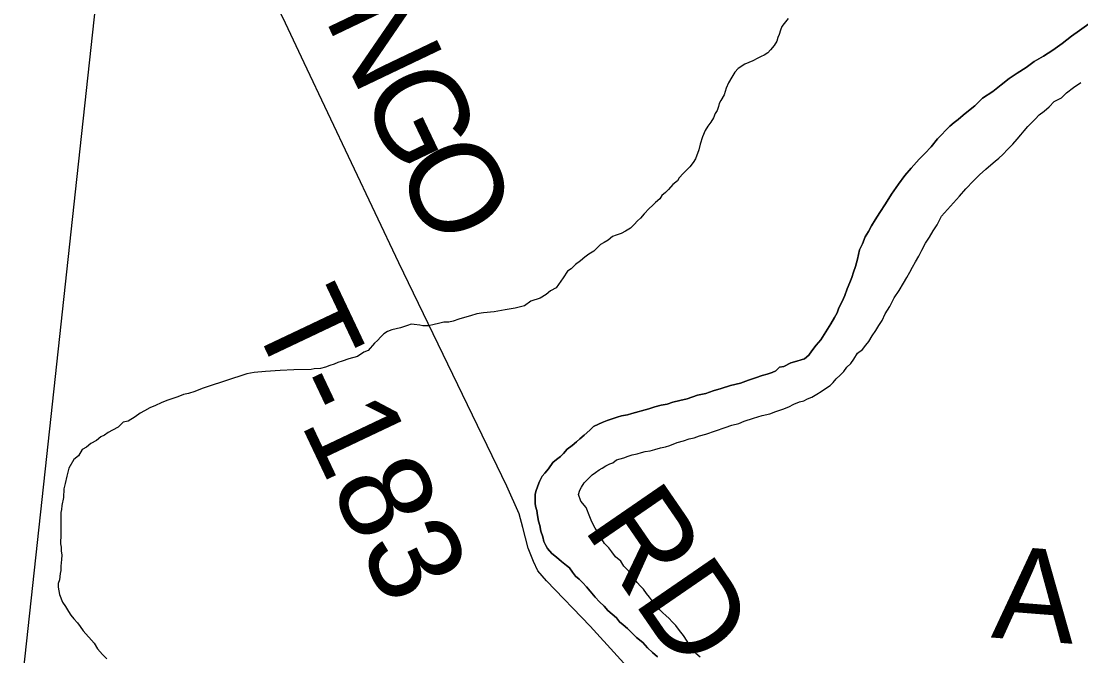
# Model space of a CAD drawing. Extents: x 0 to 34, y 0 to 22.
# Drawn here: x 4.269 to 4.921, y 16.386 to 16.776 of the extents above; entities that cross this region are included whole.
import ezdxf

# ---------------------------------------------------------------- set-up
doc = ezdxf.new("R2010")
doc.units = 0
for name, color, linetype in [('GM_X_Major_River', 7, 'Continuous'), ('GM_X_Minor_River', 7, 'Continuous'), ('GM_X_State_Route', 7, 'Continuous'), ('GM_X_Township_Road', 7, 'Continuous'), ('GM_X_Township_Road_Text', 7, 'Continuous')]:
    doc.layers.add(name, color=color, linetype=linetype)

msp = doc.modelspace()

# ---------------------------------------------------------------- linework, layer by layer
at = {"layer": 'GM_X_Major_River'}
for points in [[(4.92578, 16.77455), (4.92003, 16.77043), (4.91505, 16.76707), (4.90929, 16.76258), (4.90354, 16.75846), (4.89779, 16.75473), (4.89205, 16.75138), (4.88706, 16.74763), (4.8817, 16.74428), (4.87672, 16.74091), (4.87173, 16.73717), (4.86674, 16.73305), (4.86023, 16.72895), (4.85561, 16.72406), (4.85177, 16.72107), (4.84832, 16.71844), (4.84525, 16.71582), (4.84294, 16.71395), (4.84026, 16.7117), (4.83256, 16.70381), (4.8287, 16.69891), (4.82485, 16.69477), (4.82138, 16.69139), (4.81637, 16.68575), (4.81252, 16.68124), (4.80865, 16.67596), (4.8044, 16.66993), (4.80053, 16.66389), (4.79704, 16.65861), (4.79433, 16.65408), (4.792, 16.65031), (4.79006, 16.64691), (4.78812, 16.64351), (4.78655, 16.63935), (4.7846, 16.63557), (4.78339, 16.62988), (4.78219, 16.62534)], [(4.78219, 16.62534), (4.78339, 16.62988), (4.7846, 16.63557), (4.78655, 16.63935), (4.78812, 16.64351), (4.79006, 16.64691), (4.792, 16.65031), (4.79433, 16.65408), (4.79704, 16.65861), (4.80053, 16.66389), (4.8044, 16.66993), (4.80865, 16.67596), (4.81252, 16.68124), (4.81637, 16.68575), (4.82138, 16.69139), (4.82485, 16.69477), (4.8287, 16.69891), (4.83256, 16.70381), (4.84026, 16.7117), (4.84294, 16.71395), (4.84525, 16.71582), (4.84832, 16.71844), (4.85177, 16.72107), (4.85561, 16.72406), (4.86023, 16.72895), (4.86674, 16.73305), (4.87173, 16.73717), (4.87672, 16.74091), (4.8817, 16.74428), (4.88706, 16.74763), (4.89205, 16.75138), (4.89779, 16.75473), (4.90354, 16.75846), (4.90929, 16.76258), (4.91505, 16.76707), (4.92003, 16.77043), (4.92578, 16.77455)], [(4.89815, 16.7209), (4.90122, 16.72352), (4.9043, 16.7269), (4.90889, 16.72913), (4.91197, 16.73214), (4.91619, 16.73551), (4.92079, 16.73849)], [(4.89815, 16.7209), (4.90122, 16.72352), (4.9043, 16.7269), (4.90889, 16.72913), (4.91197, 16.73214), (4.91619, 16.73551), (4.92079, 16.73849)], [(4.61657, 16.47715), (4.6132, 16.48099), (4.61173, 16.48519), (4.61252, 16.48784), (4.61369, 16.48973), (4.61524, 16.49237), (4.61793, 16.495), (4.62024, 16.49725), (4.62215, 16.49875), (4.62445, 16.50024), (4.62637, 16.50136), (4.62867, 16.50286), (4.63096, 16.50397), (4.63287, 16.50471), (4.63518, 16.50658), (4.63975, 16.50766), (4.64242, 16.50877), (4.64471, 16.50951), (4.64776, 16.51023), (4.65043, 16.51096), (4.65272, 16.51169), (4.65577, 16.51204), (4.65882, 16.51276), (4.66225, 16.51386), (4.6653, 16.51458), (4.66797, 16.51531), (4.67256, 16.51716), (4.67637, 16.51826), (4.6798, 16.51935), (4.68285, 16.52008), (4.68629, 16.52118), (4.6901, 16.52227), (4.70194, 16.52632), (4.70614, 16.52779), (4.71033, 16.52888), (4.71377, 16.53036), (4.71949, 16.53219), (4.72483, 16.53365), (4.72941, 16.53473), (4.73323, 16.53621), (4.73743, 16.53768), (4.74124, 16.53915), (4.7443, 16.54064), (4.74774, 16.54212), (4.75041, 16.54284), (4.75271, 16.54396), (4.75538, 16.54507), (4.75844, 16.54693), (4.76112, 16.54842), (4.76381, 16.55029), (4.76649, 16.55216), (4.76841, 16.55404), (4.77034, 16.55629), (4.77265, 16.55855), (4.77496, 16.5608), (4.77689, 16.56344), (4.7792, 16.56569), (4.78113, 16.56833), (4.78345, 16.5721), (4.78652, 16.57435), (4.78846, 16.57699), (4.79038, 16.57924), (4.79233, 16.58264), (4.79465, 16.58604), (4.79658, 16.58905), (4.79852, 16.59207), (4.80047, 16.59623), (4.80319, 16.60076), (4.80591, 16.60605), (4.80901, 16.61057), (4.81172, 16.6151), (4.81366, 16.6185), (4.81561, 16.6219), (4.81716, 16.62492), (4.8191, 16.62832), (4.82105, 16.63172), (4.82299, 16.6355), (4.82532, 16.63965), (4.82765, 16.64342), (4.82997, 16.6472), (4.8323, 16.65097), (4.83502, 16.65626), (4.8462, 16.66867), (4.85005, 16.67319), (4.85468, 16.67808), (4.85852, 16.68183), (4.86236, 16.68521), (4.86544, 16.68783), (4.86812, 16.69008), (4.87043, 16.69195), (4.87274, 16.69421), (4.87582, 16.69759), (4.8789, 16.7006), (4.88159, 16.70361), (4.8839, 16.70624), (4.88584, 16.70888), (4.88815, 16.71151), (4.89046, 16.71376), (4.89277, 16.71602), (4.89508, 16.71865), (4.89815, 16.7209)], [(4.61657, 16.47715), (4.6132, 16.48099), (4.61173, 16.48519), (4.61252, 16.48784), (4.61369, 16.48973), (4.61524, 16.49237), (4.61793, 16.495), (4.62024, 16.49725), (4.62215, 16.49875), (4.62445, 16.50024), (4.62637, 16.50136), (4.62867, 16.50286), (4.63096, 16.50397), (4.63287, 16.50471), (4.63518, 16.50658), (4.63975, 16.50766), (4.64242, 16.50877), (4.64471, 16.50951), (4.64776, 16.51023), (4.65043, 16.51096), (4.65272, 16.51169), (4.65577, 16.51204), (4.65882, 16.51276), (4.66225, 16.51386), (4.6653, 16.51458), (4.66797, 16.51531), (4.67256, 16.51716), (4.67637, 16.51826), (4.6798, 16.51935), (4.68285, 16.52008), (4.68629, 16.52118), (4.6901, 16.52227), (4.70194, 16.52632), (4.70614, 16.52779), (4.71033, 16.52888), (4.71377, 16.53036), (4.71949, 16.53219), (4.72483, 16.53365), (4.72941, 16.53473), (4.73323, 16.53621), (4.73743, 16.53768), (4.74124, 16.53915), (4.7443, 16.54064), (4.74774, 16.54212), (4.75041, 16.54284), (4.75271, 16.54396), (4.75538, 16.54507), (4.75844, 16.54693), (4.76112, 16.54842), (4.76381, 16.55029), (4.76649, 16.55216), (4.76841, 16.55404), (4.77034, 16.55629), (4.77265, 16.55855), (4.77496, 16.5608), (4.77689, 16.56344), (4.7792, 16.56569), (4.78113, 16.56833), (4.78345, 16.5721), (4.78652, 16.57435), (4.78846, 16.57699), (4.79038, 16.57924), (4.79233, 16.58264), (4.79465, 16.58604), (4.79658, 16.58905), (4.79852, 16.59207), (4.80047, 16.59623), (4.80319, 16.60076), (4.80591, 16.60605), (4.80901, 16.61057), (4.81172, 16.6151), (4.81366, 16.6185), (4.81561, 16.6219), (4.81716, 16.62492), (4.8191, 16.62832), (4.82105, 16.63172), (4.82299, 16.6355), (4.82532, 16.63965), (4.82765, 16.64342), (4.82997, 16.6472), (4.8323, 16.65097), (4.83502, 16.65626), (4.8462, 16.66867), (4.85005, 16.67319), (4.85468, 16.67808), (4.85852, 16.68183), (4.86236, 16.68521), (4.86544, 16.68783), (4.86812, 16.69008), (4.87043, 16.69195), (4.87274, 16.69421), (4.87582, 16.69759), (4.8789, 16.7006), (4.88159, 16.70361), (4.8839, 16.70624), (4.88584, 16.70888), (4.88815, 16.71151), (4.89046, 16.71376), (4.89277, 16.71602), (4.89508, 16.71865), (4.89815, 16.7209)], [(4.78219, 16.62534), (4.78101, 16.62193), (4.77983, 16.61852), (4.77865, 16.6155), (4.77709, 16.61171), (4.77552, 16.60755), (4.77395, 16.60377), (4.77201, 16.59999), (4.77083, 16.59696), (4.76927, 16.59394), (4.76695, 16.59017), (4.76075, 16.58036), (4.75805, 16.57697), (4.75534, 16.57358), (4.75341, 16.57094), (4.75072, 16.56869), (4.74881, 16.56795), (4.74614, 16.56722), (4.74233, 16.56613), (4.73812, 16.5639), (4.73546, 16.56355), (4.73315, 16.5613), (4.73085, 16.56018), (4.7278, 16.55908), (4.72475, 16.55836), (4.72055, 16.55688), (4.71635, 16.55541), (4.71139, 16.55357), (4.70529, 16.55212), (4.69956, 16.55029), (4.6946, 16.54883), (4.69003, 16.54736), (4.68507, 16.54628), (4.67858, 16.54408), (4.67401, 16.54299), (4.66981, 16.5419), (4.66638, 16.5408), (4.66257, 16.54009), (4.65875, 16.53899), (4.65494, 16.5379), (4.64464, 16.53498), (4.64197, 16.53425), (4.63816, 16.53353), (4.63549, 16.5328), (4.63244, 16.5317), (4.62938, 16.5306), (4.62633, 16.52949), (4.62403, 16.52838), (4.62097, 16.5269), (4.61867, 16.52464), (4.61521, 16.52164), (4.61252, 16.51939), (4.6106, 16.51751), (4.60791, 16.51527), (4.60484, 16.51302), (4.60253, 16.51039), (4.60061, 16.50851), (4.5983, 16.50664), (4.596, 16.50476), (4.59329, 16.50099), (4.59098, 16.49836), (4.58944, 16.49648), (4.58787, 16.49308), (4.5867, 16.49043), (4.58552, 16.48702), (4.58512, 16.48513), (4.58509, 16.48284), (4.58505, 16.4798), (4.58541, 16.4779), (4.58614, 16.47523), (4.58648, 16.47219), (4.5872, 16.46875), (4.58793, 16.46609), (4.58865, 16.46266), (4.58975, 16.45922), (4.59047, 16.45617), (4.59159, 16.45388), (4.5927, 16.45196), (4.59533, 16.44889), (4.59834, 16.44658), (4.60135, 16.44388), (4.60436, 16.44156), (4.60624, 16.44002), (4.60811, 16.43734), (4.60999, 16.43503), (4.61224, 16.43311), (4.6145, 16.4308), (4.61675, 16.42849), (4.619, 16.4258), (4.62199, 16.42197), (4.62462, 16.41927), (4.62763, 16.41658), (4.62988, 16.41389), (4.63251, 16.41158), (4.63515, 16.40927), (4.63702, 16.40696), (4.63928, 16.40504), (4.64191, 16.40272), (4.64454, 16.40003), (4.64755, 16.39733), (4.65131, 16.39425)], [(4.65131, 16.39425), (4.64755, 16.39733), (4.64454, 16.40003), (4.64191, 16.40272), (4.63928, 16.40504), (4.63702, 16.40696), (4.63515, 16.40927), (4.63251, 16.41158), (4.62988, 16.41389), (4.62763, 16.41658), (4.62462, 16.41927), (4.62199, 16.42197), (4.619, 16.4258), (4.61675, 16.42849), (4.6145, 16.4308), (4.61224, 16.43311), (4.60999, 16.43503), (4.60811, 16.43734), (4.60624, 16.44002), (4.60436, 16.44156), (4.60135, 16.44388), (4.59834, 16.44658), (4.59533, 16.44889), (4.5927, 16.45196), (4.59159, 16.45388), (4.59047, 16.45617), (4.58975, 16.45922), (4.58865, 16.46266), (4.58793, 16.46609), (4.5872, 16.46875), (4.58648, 16.47219), (4.58614, 16.47523), (4.58541, 16.4779), (4.58505, 16.4798), (4.58509, 16.48284), (4.58512, 16.48513), (4.58552, 16.48702), (4.5867, 16.49043), (4.58787, 16.49308), (4.58944, 16.49648), (4.59098, 16.49836), (4.59329, 16.50099), (4.596, 16.50476), (4.5983, 16.50664), (4.60061, 16.50851), (4.60253, 16.51039), (4.60484, 16.51302), (4.60791, 16.51527), (4.6106, 16.51751), (4.61252, 16.51939), (4.61521, 16.52164), (4.61867, 16.52464), (4.62097, 16.5269), (4.62403, 16.52838), (4.62633, 16.52949), (4.62938, 16.5306), (4.63244, 16.5317), (4.63549, 16.5328), (4.63816, 16.53353), (4.64197, 16.53425), (4.64464, 16.53498), (4.65494, 16.5379), (4.65875, 16.53899), (4.66257, 16.54009), (4.66638, 16.5408), (4.66981, 16.5419), (4.67401, 16.54299), (4.67858, 16.54408), (4.68507, 16.54628), (4.69003, 16.54736), (4.6946, 16.54883), (4.69956, 16.55029), (4.70529, 16.55212), (4.71139, 16.55357), (4.71635, 16.55541), (4.72055, 16.55688), (4.72475, 16.55836), (4.7278, 16.55908), (4.73085, 16.56018), (4.73315, 16.5613), (4.73546, 16.56355), (4.73812, 16.5639), (4.74233, 16.56613), (4.74614, 16.56722), (4.74881, 16.56795), (4.75072, 16.56869), (4.75341, 16.57094), (4.75534, 16.57358), (4.75805, 16.57697), (4.76075, 16.58036), (4.76695, 16.59017), (4.76927, 16.59394), (4.77083, 16.59696), (4.77201, 16.59999), (4.77395, 16.60377), (4.77552, 16.60755), (4.77709, 16.61171), (4.77865, 16.6155), (4.77983, 16.61852), (4.78101, 16.62193), (4.78219, 16.62534)], [(4.68655, 16.38509), (4.68392, 16.3874), (4.68281, 16.38969), (4.68093, 16.392), (4.67869, 16.39507), (4.67645, 16.39851), (4.67383, 16.40158), (4.67158, 16.40465), (4.66933, 16.40696), (4.66745, 16.40888), (4.66558, 16.41081), (4.66369, 16.41235), (4.66181, 16.41427), (4.66032, 16.41657), (4.65732, 16.41965), (4.65544, 16.42195), (4.65357, 16.42425), (4.6517, 16.42694), (4.64983, 16.42886), (4.64795, 16.43116), (4.64645, 16.43308), (4.64496, 16.435), (4.64346, 16.43692), (4.64159, 16.43922), (4.63971, 16.44114), (4.63785, 16.44421), (4.63446, 16.44691), (4.63221, 16.44998), (4.63034, 16.45228), (4.62771, 16.45497), (4.62622, 16.45765), (4.62473, 16.45995), (4.62324, 16.46263), (4.62212, 16.46454), (4.61989, 16.46837), (4.61879, 16.47142), (4.61657, 16.47715)], [(4.68655, 16.38509), (4.68392, 16.3874), (4.68281, 16.38969), (4.68093, 16.392), (4.67869, 16.39507), (4.67645, 16.39851), (4.67383, 16.40158), (4.67158, 16.40465), (4.66933, 16.40696), (4.66745, 16.40888), (4.66558, 16.41081), (4.66369, 16.41235), (4.66181, 16.41427), (4.66032, 16.41657), (4.65732, 16.41965), (4.65544, 16.42195), (4.65357, 16.42425), (4.6517, 16.42694), (4.64983, 16.42886), (4.64795, 16.43116), (4.64645, 16.43308), (4.64496, 16.435), (4.64346, 16.43692), (4.64159, 16.43922), (4.63971, 16.44114), (4.63785, 16.44421), (4.63446, 16.44691), (4.63221, 16.44998), (4.63034, 16.45228), (4.62771, 16.45497), (4.62622, 16.45765), (4.62473, 16.45995), (4.62324, 16.46263), (4.62212, 16.46454), (4.61989, 16.46837), (4.61879, 16.47142), (4.61657, 16.47715)], [(4.65131, 16.39425), (4.65431, 16.39079), (4.65732, 16.3881), (4.66033, 16.3854)], [(4.66033, 16.3854), (4.65732, 16.3881), (4.65431, 16.39079), (4.65131, 16.39425)]]:
    msp.add_lwpolyline(points, dxfattribs=at)
at = {"layer": 'GM_X_Minor_River'}
for points in [[(4.74069, 16.77788), (4.73838, 16.77487), (4.73683, 16.77298), (4.73605, 16.77071), (4.73526, 16.76806), (4.73447, 16.76617), (4.73368, 16.7639), (4.73213, 16.76126), (4.72982, 16.75862), (4.72828, 16.75674), (4.72598, 16.75525), (4.72407, 16.75451), (4.72215, 16.75339), (4.71909, 16.75191), (4.71413, 16.74969), (4.70991, 16.74708), (4.70798, 16.74482), (4.70605, 16.7418), (4.70411, 16.7384), (4.70255, 16.735), (4.70135, 16.73083), (4.69941, 16.72743), (4.69825, 16.72555), (4.69785, 16.72365), (4.69706, 16.72138), (4.6959, 16.71949), (4.69472, 16.71685), (4.69317, 16.7142), (4.69124, 16.71156), (4.68969, 16.70892), (4.68812, 16.70514), (4.68655, 16.7006), (4.68575, 16.69719), (4.68378, 16.69151), (4.68223, 16.68924), (4.6803, 16.68661), (4.67799, 16.68435), (4.67606, 16.68247), (4.67375, 16.67984), (4.67259, 16.67795), (4.6699, 16.6757), (4.6672, 16.67269), (4.66528, 16.67082), (4.66298, 16.66894), (4.66181, 16.66706), (4.65913, 16.66481), (4.6572, 16.66293), (4.65528, 16.66105), (4.6522, 16.65767), (4.64988, 16.65504), (4.64797, 16.65354), (4.64604, 16.65128), (4.64373, 16.64903), (4.64067, 16.64716), (4.63799, 16.64567), (4.63493, 16.64457), (4.63265, 16.64383), (4.62996, 16.64159), (4.62766, 16.64009), (4.62536, 16.63898), (4.62344, 16.6371), (4.62113, 16.63485), (4.61807, 16.63298), (4.61576, 16.63111), (4.61308, 16.62886), (4.61001, 16.62662), (4.60732, 16.62399), (4.60502, 16.6225), (4.60231, 16.61835), (4.59805, 16.61231), (4.59461, 16.61046), (4.59192, 16.60821), (4.58809, 16.60597), (4.58237, 16.60414), (4.57853, 16.60114), (4.57281, 16.59969), (4.56672, 16.59862), (4.55986, 16.59756), (4.55339, 16.59688)], [(4.55339, 16.59688), (4.5492, 16.59617), (4.54539, 16.59507), (4.54157, 16.59398), (4.53814, 16.59288), (4.5347, 16.59178), (4.53203, 16.59105), (4.52899, 16.59109), (4.52556, 16.59037), (4.52289, 16.58964), (4.51946, 16.58892), (4.51604, 16.58896), (4.51415, 16.58936), (4.51073, 16.58978), (4.50883, 16.58981), (4.50654, 16.58907), (4.50234, 16.5876), (4.49701, 16.58652), (4.49433, 16.58542), (4.49203, 16.58392), (4.49011, 16.58205), (4.48818, 16.57979), (4.48626, 16.57829), (4.48241, 16.57377), (4.47973, 16.57266), (4.4759, 16.57005), (4.47056, 16.56859), (4.46636, 16.56712), (4.46369, 16.56639), (4.4614, 16.56528), (4.45873, 16.56455), (4.45606, 16.56344), (4.45301, 16.56272), (4.4492, 16.56238), (4.4473, 16.56202), (4.43665, 16.56177), (4.42828, 16.56149), (4.41915, 16.56084), (4.4123, 16.56016), (4.40773, 16.55945), (4.40353, 16.55798), (4.39895, 16.55652), (4.39208, 16.55432), (4.38636, 16.55248), (4.38025, 16.55027), (4.37567, 16.54843), (4.37185, 16.54733), (4.3688, 16.54661), (4.36536, 16.54513), (4.36155, 16.54404), (4.35849, 16.54293), (4.35505, 16.54145), (4.35162, 16.53997), (4.34818, 16.53849), (4.34473, 16.53663), (4.34205, 16.53514), (4.33899, 16.5329), (4.33477, 16.53029), (4.33172, 16.52956), (4.32865, 16.52656), (4.3252, 16.5247), (4.32252, 16.52321), (4.32022, 16.52172), (4.31793, 16.52061), (4.31524, 16.51836), (4.3118, 16.5165), (4.30911, 16.51425), (4.30643, 16.51276), (4.30411, 16.50898), (4.30142, 16.50674), (4.29831, 16.50145), (4.29711, 16.49652), (4.29592, 16.49198), (4.29512, 16.48856), (4.29505, 16.48324), (4.29385, 16.47832), (4.29383, 16.47603), (4.29342, 16.47414), (4.2934, 16.47224), (4.29337, 16.46958), (4.29333, 16.46616), (4.29329, 16.46274), (4.29324, 16.45894), (4.29321, 16.45665), (4.29319, 16.45476), (4.29355, 16.45285), (4.29352, 16.45057), (4.29387, 16.44791), (4.29384, 16.44525), (4.2934, 16.44107), (4.29337, 16.43841), (4.29297, 16.43651), (4.29255, 16.43272), (4.29176, 16.43044), (4.29173, 16.42816), (4.29244, 16.42359), (4.29428, 16.41901), (4.29615, 16.41633), (4.29801, 16.41326), (4.29951, 16.41097), (4.30138, 16.40866)], [(4.30138, 16.40866), (4.30363, 16.40636), (4.30513, 16.40406), (4.30699, 16.40137), (4.31374, 16.39369), (4.31598, 16.39024), (4.31898, 16.38679), (4.32161, 16.38409)]]:
    msp.add_lwpolyline(points, dxfattribs=at)
at = {"layer": 'GM_X_State_Route'}
msp.add_lwpolyline([(4.27027, 16.37631), (4.28475, 16.50856), (4.30229, 16.67131), (4.32159, 16.84896), (4.33629, 16.97683), (4.33651, 16.99175), (4.33541, 17.00842), (4.33322, 17.02486), (4.32861, 17.04614), (4.2944, 17.1909), (4.28409, 17.24968), (4.25492, 17.42119), (4.23825, 17.5234), (4.22575, 17.62977), (4.2229, 17.65346), (4.21763, 17.68154), (4.20535, 17.73834), (4.16981, 17.88475)], dxfattribs=at)
at = {"layer": 'GM_X_Township_Road'}
msp.add_lwpolyline([(4.65016, 16.36992), (4.61886, 16.40425), (4.59207, 16.43209), (4.5868, 16.43819), (4.58417, 16.4439), (4.5808, 16.45227), (4.57745, 16.46482), (4.57521, 16.47318), (4.56771, 16.49031), (4.50127, 16.62771), (4.44309, 16.75065), (4.43145, 16.77501), (4.41794, 16.80242), (4.36314, 16.91774), (4.34476, 16.95808), (4.33629, 16.97683)], dxfattribs=at)

# ---------------------------------------------------------------- texts
at = {"layer": 'GM_X_Township_Road_Text'}
for s, height, rotation, p in [('N', 0.05682, 295.52807, (4.45527, 16.77832)), ('G', 0.05682, 295.5191, (4.47682, 16.7332)), ('O', 0.05682, 295.5222, (4.49837, 16.68808)), ('T-183', 0.056818, 295.34708, (4.40978, 16.59404)), ('RD', 0.056818, 304.50911, (4.61396, 16.46479)), ('A', 0.05682, 355.5443, (4.86526, 16.39728))]:
    msp.add_text(s, height=height, rotation=rotation, dxfattribs=at).set_placement(p)

doc.saveas('drawing.dxf')
